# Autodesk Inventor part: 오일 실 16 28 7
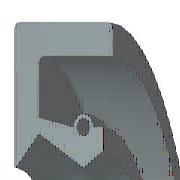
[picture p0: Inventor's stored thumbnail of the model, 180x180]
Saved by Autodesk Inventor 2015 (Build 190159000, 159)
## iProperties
Created: 2012-02
Part Number: 오일 실 16 28 7
Material: 고무
Description: 오일-실
Document SubType Name: Modeling
Standard: KS B 2804
Designer: mduedu
Standards Organization: KS
Language: ko-KR
Size Designation: D - 16 28 7
Categories: <MemberInstance><Categories><Category DisplayName="샤프트 부품" InternalName="7f7aeb1f-a693-4053-b835-cee3144e0d98" Mnemonic="SHFT"><Category DisplayName="실링" Intern
Density: 0.93 g/cm^3
Appearance: 고무 - 검은색 - 버전 1.1
IsCustomPart: 1
Author: mduedu
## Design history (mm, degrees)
revolve "본체" stored, may be unused: angle "d17" = 90 deg
revolve "스프링1" stored, may be unused: angle "d18" = 90 deg
fillet "모깎기3" dims "d43" = 0.5
body "Solid1"
sketch "스케치1"
  geometry: L1 (0, 14)-(7, 14); L2 (7, 12.25)-(1.75, 12.25); L3 (1.75, 9.75)-(4.9, 8); L4 (4.9, 8)-(0, 8); L5 (0, 0)-(9.586, 0) reference; L6 (4.9, 8)-(6.3, 8.875); L7 (0, 18)-(0, -3) reference; L8 (-1.941, 0)-(11.507, 0) reference; L9 (4.2, 10.1)-(1.75, 10.59); L10 (1.75, 10.59)-(1.75, 12.25); L11 (0, 14)-(0, 8.088); L12 (4.9, 8)-(0, 8); L13 (1.75, 9.75)-(0.152, 8.028); L14 (7, 14)-(7, 12.25); L15 (5.6, 10.1)-(6.3, 10.1); L16 (6.3, 10.1)-(6.3, 8.875); C1 r 0.455 at (4.9, 10.1); A1 r 0.7 centre (4.9, 10.1) between (5.6, 10.1) and (4.2, 10.1); A2 r 0.088 centre (0.088, 8.088) between (0, 8.088) and (0.152, 8.028); 1 further point
  constraints: 28 end point, 5 horizontal alignment, 5 point on line, 4 point on circle, 4 vertical alignment, 3 centre point, 3 tangent, 2 collinear, 2 horizontal, 2 perpendicular, 1 coincident, 1 parallel
  dimensions: "d0" = 28 diameter of L1 L5 (= SD2); "d1" = 1.75 distance of L1.end L2.start (= SD); "d2" = 0.91 diameter of C1 (= SPDI); "d3" = 1.4 diameter of A1 (= SPDA); "d4" = 16 diameter of L3.end L5 (= NND); "d5" = 19.5 diameter of L3.start L5 (= TKDM); "d7" = 21.18 diameter of L9.end L5 (= TKDM + 0.24 x SWDT); "d8" = 1.75 distance between parallel lines of L11 L10 (= SD); "d9" = 4.9 distance from line of L11 C1.centre (= SPDST); "d10" = 20.2 diameter of C1.centre L5 (= HLDM); "d11" = 0.0875 radius of A2 (= 0.25 x LAB); "d12" = 6.3 distance between parallel lines of L11 L16 (= SDI); "d13" = 17.75 diameter of L6.end L5 (= ABDM); "d14" = 7 distance from line of L11 L1.end (= SWDT)
fillet "모깎기1" dims "d6" = 0.3 (= RR)
other parameters: "SD2" = 28 [user parameter; used in 1 equation term], "SWDT" = 7 [user parameter; used in 2 equation terms], "RR" = 0.3 [user parameter; used in 1 equation term], "SD" = 1.75 [user parameter; used in 2 equation terms], "NND" = 16 [user parameter; used in 1 equation term], "SPDA" = 1.4 [user parameter; used in 1 equation term], "SPDI" = 0.91 [user parameter; used in 1 equation term], "TKDM" = 19.5 [user parameter; used in 2 equation terms], "HLDM" = 20.2 [user parameter; used in 1 equation term], "ABDM" = 17.75 [user parameter; used in 1 equation term], "SDI" = 6.3 [user parameter; used in 1 equation term], "SPDST" = 4.9 [user parameter; used in 1 equation term], "LAB" = 0.35 [user parameter; used in 1 equation term], "d15" = 0, "d16" = 0, "d19" = 0
